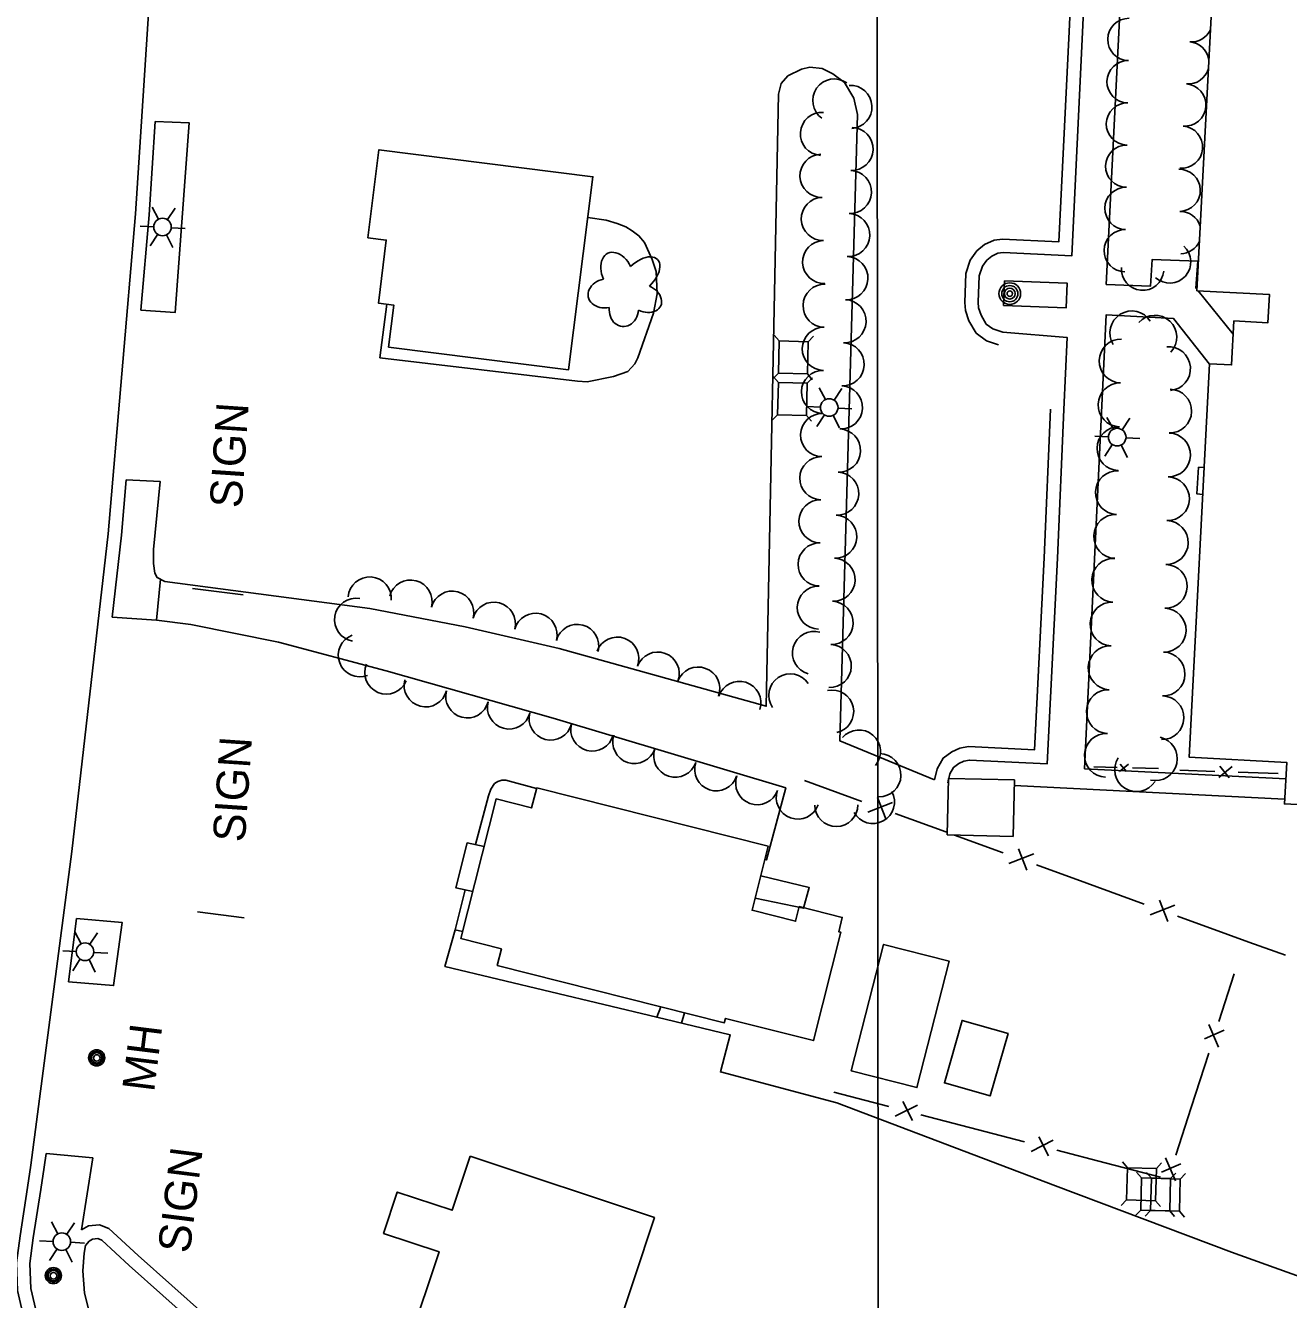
# Model space of a CAD drawing. Extents: x 189384 to 193282, y 256970 to 260388.
# Drawn here: x 190987.6 to 191223.1, y 259169.2 to 259406.6 of the extents above; entities that cross this region are included whole.
import ezdxf

# ---------------------------------------------------------------- set-up
doc = ezdxf.new("R2010")
doc.units = 0
for name, color, linetype in [('E_DRN_Grate', 7, 'Continuous'), ('E_DWY', 7, 'Continuous'), ('E_LAND_Vegetation', 7, 'Continuous'), ('E_MAP_GridLines', 7, 'Continuous'), ('E_MISCPROP', 7, 'Continuous'), ('E_MISCPROP_HvyDash', 7, 'Continuous'), ('E_MISCPROP_HvyLine', 7, 'Continuous'), ('E_MISCPROP_Railing', 7, 'Continuous'), ('E_PATH_Sidewalk', 7, 'Continuous'), ('E_RDWY', 7, 'Continuous'), ('E_UTL_AboveGroundPipe', 7, 'Continuous')]:
    doc.layers.add(name, color=color, linetype=linetype)

# ---------------------------------------------------------------- blocks, each defined once
blk = doc.blocks.new('MHO_15')
at = {"layer": 'E_DRN_Grate'}
for centre, radius in [((0.04, -0.06), 1.5), ((0.04, -0.06), 1.22), ((0.04, -0.07), 0.968), ((0.01, -0.08), 0.605)]:
    blk.add_circle(centre, radius, dxfattribs=at)
blk = doc.blocks.new('MHO_16')
at = {"layer": 'E_DRN_Grate'}
for centre, radius in [((0.04, -0.06), 1.5), ((0.04, -0.06), 1.22), ((0.04, -0.07), 0.968), ((0.01, -0.08), 0.605)]:
    blk.add_circle(centre, radius, dxfattribs=at)
blk = doc.blocks.new('MHT_14')
at = {"layer": 'E_DRN_Grate'}
blk.add_text('MH', height=6, rotation=360, dxfattribs=at).set_placement((-5.61, -3.06))
blk = doc.blocks.new('PED')
at = {"layer": 'E_UTL_AboveGroundPipe'}
for p, q in [((-2.34, 2.71), (-3.29, 3.77)), ((3.06, 2.71), (4.02, 3.77)), ((-3.29, -4.35), (-2.34, -3.29)), ((4.02, -4.35), (3.06, -3.29))]:
    blk.add_line(p, q, dxfattribs=at)
blk.add_lwpolyline([(-2.34, -3.29), (3.06, -3.29), (3.06, 2.71), (-2.34, 2.71)], close=True, dxfattribs=at)
blk = doc.blocks.new('LTP')
at = {"layer": 'E_MISCPROP'}
for p, q in [((-0.78, 1.46), (-1.98, 3.76)), ((0.86, 1.37), (2.22, 3.6)), ((-1.61, 0.09), (-4.22, 0.17)), ((1.66, 0), (4.18, -0.06)), ((-0.86, -1.4), (-2.22, -3.59)), ((0.78, -1.44), (2.02, -3.62))]:
    blk.add_line(p, q, dxfattribs=at)
blk.add_circle((0.02, 0.01), 1.64, dxfattribs=at)
blk = doc.blocks.new('POLE')
at = {"layer": 'E_MISCPROP'}
for radius in [2.02, 1.51, 1.01, 0.504]:
    blk.add_circle((0.03, -0.09), radius, dxfattribs=at)
blk = doc.blocks.new('TREE')
at = {"layer": 'E_LAND_Vegetation'}
for centre, major_axis, ratio in [((-1.07, 3.38), (0.91, -3.32), 0.782863), ((2.88, 1.66), (-3.52, -1.95), 0.691916), ((-3.74, -0.07), (3.29, -0.08), 0.832022), ((2.54, -2.64), (-3.34, 3.06), 0.560249), ((-1.48, -3.66), (1.2, 3.24), 0.716896)]:
    blk.add_ellipse(centre, major_axis=major_axis, ratio=ratio, start_param=1.570796, end_param=4.712389, dxfattribs=at)
blk = doc.blocks.new('SIGN')
at = {"layer": 'E_MISCPROP'}
blk.add_text('SIGN', height=6, rotation=0, dxfattribs=at).set_placement((0, -3))
blk = doc.blocks.new('SIGN_1')
at = {"layer": 'E_MISCPROP'}
blk.add_text('SIGN', height=6, rotation=360, dxfattribs=at).set_placement((-9.61, -3.01))

msp = doc.modelspace()

# ---------------------------------------------------------------- linework, layer by layer
at = {"layer": 'E_DWY'}
for points in [[(191169.01, 259347.09), (191166.8, 259347.84), (191164.86, 259349.29), (191163.51, 259351.61), (191162.86, 259353.49), (191162.74, 259355), (191162.95, 259360.41), (191163.78, 259362.92), (191165.02, 259364.61), (191166.44, 259365.79), (191168.22, 259366.62), (191169.77, 259366.82), (191180.31, 259366.31), (191182.18, 259405.49), (191184.13, 259447.55), (191185.9, 259490.73)], [(191169.82, 259349.45), (191167.98, 259350.08), (191166.76, 259350.99), (191165.79, 259352.65), (191165.33, 259354.01), (191165.24, 259355.05), (191165.44, 259359.96), (191166.03, 259361.76), (191166.85, 259362.88), (191167.79, 259363.66), (191168.93, 259364.19), (191169.88, 259364.31), (191182.69, 259363.69), (191184.68, 259405.37), (191186.63, 259447.44), (191188.4, 259490.63)], [(191006.37, 259321.93), (191012.7, 259321.64), (191011.49, 259308.96), (191011.47, 259306.34), (191011.72, 259304.53), (191012.18, 259303.72), (191013.58, 259303), (191051.8, 259297.98), (191069.57, 259294.53), (191087.1, 259290.48), (191125.73, 259279.75), (191128.01, 259393.82), (191128.53, 259395.79), (191129.77, 259397.26), (191132.28, 259398.5), (191133.84, 259398.85), (191136.13, 259398.59), (191138.15, 259397.63), (191140.33, 259395.99), (191142.05, 259393.07), (191142.76, 259390.06), (191139.44, 259273.33), (191157.12, 259266.03)], [(191011.76, 259388.74), (191018.1, 259388.51), (191015.49, 259353.13), (191009.1, 259353.57)], [(191054.97, 259354.7), (191053.69, 259344.69), (191090.5, 259340.33), (191092.35, 259340.22), (191097.25, 259341.2), (191099.92, 259342.17), (191101.2, 259343.55), (191101.76, 259344.69), (191104.68, 259353.02), (191105.38, 259356.62), (191105.2, 259360.8), (191104.45, 259363), (191103, 259366.16), (191101.98, 259367.43), (191100.72, 259368.33), (191099.52, 259369.1), (191097.94, 259369.71), (191095.88, 259370.32), (191092.44, 259370.86)], [(191181.22, 259335.03), (191181.83, 259348.49), (191169.82, 259349.45)], [(191157.12, 259266.03), (191157.59, 259268.09), (191158.74, 259270.09), (191160.34, 259271.22), (191161.81, 259271.94), (191163.47, 259272.22), (191175.73, 259271.62), (191177.57, 259307.44), (191178.72, 259335.14)], [(191159.75, 259266.29), (191159.94, 259267.17), (191160.63, 259268.36), (191161.62, 259269.06), (191162.58, 259269.53), (191163.62, 259269.71), (191178.1, 259269.01), (191180.06, 259307.32), (191181.22, 259335.03)], [(191003.75, 259296.38), (191012.04, 259295.81), (191018.42, 259294.98), (191034.75, 259291.71), (191054.88, 259286.33), (191086, 259277.51), (191129.37, 259264.51), (191125.77, 259251.09), (191125.47, 259251.16)], [(191159.56, 259265.48), (191159.73, 259266.22)], [(191071.52, 259253.95), (191073.96, 259263.05), (191074.37, 259264.31), (191075.03, 259265.32), (191075.7, 259265.73), (191076.42, 259265.96), (191077.16, 259265.94), (191082.89, 259264.43)], [(191067.72, 259238.05), (191069.6, 259245.5)], [(190995.6, 259228.37), (191004.01, 259227.68), (191005.61, 259239.45), (190997.14, 259240.17)], [(191105.32, 259221.78), (191119.01, 259218.52), (191117.19, 259211.6), (191138.91, 259205.83), (191179.68, 259190.35), (191212.49, 259178), (191250.88, 259164.18)], [(190998.05, 259182.13), (191000.15, 259195.57), (190991.43, 259196.39)], [(191041.42, 259147.83), (191034.49, 259154.01), (191021.16, 259166.18), (191008.62, 259177.39), (191003.17, 259182.4), (191001.43, 259183.06), (190999.35, 259182.89), (190998.05, 259182.13)], [(191039.75, 259145.97), (191032.82, 259152.15), (191019.49, 259164.33), (191006.94, 259175.54), (191001.83, 259180.24), (191001.07, 259180.52), (191000.12, 259180.44), (190999.48, 259180.07), (190998.81, 259179.24), (190998.54, 259177.81), (190998.31, 259174.49), (190998.63, 259170.35), (190999.68, 259166.21), (191001.78, 259161.45), (191004.72, 259156.99), (191007.35, 259153.66), (191010.51, 259150.69), (191013.82, 259148.31), (191019.89, 259145.1), (191026.22, 259142.62), (191030.57, 259141.21)]]:
    msp.add_lwpolyline(points, dxfattribs=at)
at = {"layer": 'E_LAND_Vegetation'}
for centre, radius, start, end in [((191193.33, 259404.03), 3.94, 89.0497, 269.0344), ((191204.99, 259407.51), 3.94, 265.5916, 334.6957), ((191204.38, 259399.66), 3.94, 9.6429, 85.5762), ((191193.2, 259396.15), 3.94, 89.0497, 269.0344), ((191204.38, 259399.66), 3.94, 265.5916, 344.4513), ((191138.42, 259392.64), 4.02, 55.0245, 235.0092), ((191141.43, 259391.45), 4.02, 273.3302, 93.3148), ((191203.78, 259391.81), 3.94, 265.5916, 85.5762), ((191193.07, 259388.28), 3.94, 89.0497, 269.0344), ((191136.11, 259386.43), 4.02, 85.9189, 265.9035), ((191141.62, 259383.62), 4.02, 267.8798, 87.8645), ((191203.17, 259383.96), 3.94, 265.5916, 85.5762), ((191136.03, 259378.61), 4.02, 91.789, 271.7737), ((191192.94, 259380.41), 3.94, 89.0497, 269.0344), ((191141.32, 259375.59), 4.02, 267.8798, 87.8645), ((191202.73, 259375.9), 3.94, 271.3648, 91.3495), ((191192.8, 259372.54), 3.94, 89.0497, 269.0344), ((191136.28, 259370.58), 4.02, 91.789, 271.7737), ((191141.01, 259367.57), 4.02, 267.5525, 87.5372), ((191202.92, 259368.03), 3.94, 18.0454, 91.3495), ((191192.67, 259364.66), 3.94, 89.0497, 269.0344), ((191136.53, 259362.54), 4.02, 91.789, 271.7737), ((191202.92, 259368.03), 3.94, 271.3648, 336.0488), ((191200.95, 259362.56), 3.94, 228.2834, 48.2681), ((191140.67, 259359.54), 4.02, 267.5525, 87.5372), ((191195.91, 259361.2), 3.94, 174.909, 354.8937), ((191136.62, 259354.4), 4.02, 88.8933, 268.878), ((191140.32, 259351.51), 4.02, 267.5525, 87.5372), ((191193.89, 259349.34), 4.08, 32.1313, 212.116), ((191198.2, 259348.53), 4.08, 317.2342, 137.2188), ((191136.47, 259346.36), 4.02, 88.8933, 268.878), ((191139.98, 259343.48), 4.02, 267.5525, 87.5372), ((191191.89, 259344.09), 4.08, 88.5722, 268.5569), ((191200.75, 259342.67), 4.08, 274.8384, 94.8231), ((191136.31, 259338.33), 4.02, 88.8933, 268.878), ((191191.69, 259335.92), 4.08, 88.5722, 268.5569), ((191139.64, 259335.44), 4.02, 267.5525, 87.5372), ((191200.96, 259334.76), 4.08, 268.574, 88.5587), ((191136.15, 259330.29), 4.02, 88.8933, 268.878), ((191139.29, 259327.41), 4.02, 267.5525, 87.5372), ((191191.48, 259327.76), 4.08, 88.5722, 268.5569), ((191200.75, 259326.59), 4.08, 268.574, 88.5587), ((191136, 259322.25), 4.02, 88.8933, 268.878), ((191138.95, 259319.38), 4.02, 267.5525, 87.5372), ((191191.21, 259319.56), 4.08, 87.6179, 267.6026), ((191200.55, 259318.42), 4.08, 268.574, 88.5587), ((191135.84, 259314.21), 4.02, 88.8933, 268.878), ((191138.6, 259311.35), 4.02, 267.5525, 87.5372), ((191190.87, 259311.4), 4.08, 87.6179, 267.6026), ((191200.34, 259310.26), 4.08, 268.574, 88.5587), ((191135.69, 259306.18), 4.02, 88.8933, 268.878), ((191138.26, 259303.32), 4.02, 267.5525, 87.5372), ((191190.53, 259303.24), 4.08, 87.6179, 267.6026), ((191200.14, 259302.09), 4.08, 268.574, 88.5587), ((191051.79, 259299.84), 4.02, 355.8605, 175.8451), ((191059.41, 259299.26), 4.02, 345.1062, 165.0909), ((191135.53, 259298.14), 4.02, 88.8933, 268.878), ((191049.23, 259295.86), 4.02, 80.2112, 260.1959), ((191067.18, 259297.19), 4.02, 345.1062, 165.0909), ((191074.95, 259295.13), 4.02, 345.1062, 165.0909), ((191082.72, 259293.06), 4.02, 345.1062, 165.0909), ((191137.91, 259295.29), 4.02, 267.5525, 87.5372), ((191190.19, 259295.07), 4.08, 87.6179, 267.6026), ((191199.93, 259293.93), 4.08, 268.574, 88.5587), ((191090.49, 259290.99), 4.02, 345.1062, 165.0909), ((191049.95, 259289.25), 4.02, 110.6208, 290.6055), ((191097.95, 259288.62), 4.02, 339.7014, 159.6861), ((191134.64, 259289.67), 4.02, 74.2741, 254.2587), ((191137.57, 259287.26), 4.02, 267.5525, 87.5372), ((191189.85, 259286.91), 4.08, 87.6179, 267.6026), ((191054.88, 259286.03), 4.02, 157.0707, 337.0554), ((191105.49, 259285.83), 4.02, 339.7014, 159.6861), ((191199.73, 259285.76), 4.08, 268.574, 88.5587), ((191113.03, 259283.04), 4.02, 339.7014, 159.6861), ((191130.22, 259281.76), 4.02, 33.9038, 213.8884), ((191062.22, 259283.65), 4.02, 165.1414, 345.126), ((191120.72, 259280.38), 4.02, 342.3555, 162.3402), ((191189.51, 259278.75), 4.08, 87.6179, 267.6026), ((191069.99, 259281.59), 4.02, 165.1414, 345.126), ((191077.76, 259279.52), 4.02, 165.1414, 345.126), ((191138.01, 259278.75), 4.02, 282.4212, 102.4059), ((191199.52, 259277.6), 4.08, 268.574, 88.5587), ((191085.53, 259277.46), 4.02, 165.1414, 345.126), ((191093.3, 259275.4), 4.02, 165.1414, 345.126), ((191101.13, 259273.08), 4.02, 161.5577, 341.5424), ((191143.02, 259271.3), 4.02, 319.8395, 139.8242), ((191189.16, 259270.59), 4.08, 87.6179, 267.6026), ((191198.29, 259269.98), 4.08, 257.4753, 77.46), ((191108.76, 259270.53), 4.02, 161.5577, 341.5424), ((191116.39, 259267.99), 4.02, 161.5577, 341.5424), ((191146.82, 259266.9), 4.02, 268.3692, 88.3539), ((191194.78, 259267.93), 4.08, 147.3836, 327.3683), ((191124.04, 259265.41), 4.02, 160.455, 340.4397), ((191131.62, 259262.72), 4.02, 160.455, 340.4397), ((191145.62, 259261.9), 4.02, 208.799, 28.7837), ((191138.79, 259261.35), 4.02, 180.2569, 0.2416)]:
    msp.add_arc(centre, radius, start, end, dxfattribs=at)
at = {"layer": 'E_MAP_GridLines'}
msp.add_line((191147.05, 258511.8), (191146.33, 259511.8), dxfattribs=at)
at = {"layer": 'E_MISCPROP'}
for p, q in [((191028.16, 259300.53), (191018.76, 259301.71)), ((191019.69, 259241.44), (191028.39, 259240.3))]:
    msp.add_line(p, q, dxfattribs=at)
at = {"layer": 'E_MISCPROP_HvyDash'}
for points in [[(191073.12, 259253.62), (191069.93, 259254.27), (191067.85, 259245.88), (191070.99, 259245.2)], [(191123.64, 259243.95), (191132.7, 259242.09), (191133.73, 259245.94), (191124.7, 259248.13)], [(191069.11, 259237.74), (191067.72, 259238.05), (191065.8, 259231.25), (191105.32, 259221.78), (191106.07, 259223.75)]]:
    msp.add_lwpolyline(points, dxfattribs=at)
at = {"layer": 'E_MISCPROP_HvyLine'}
msp.add_lwpolyline([(191249.87, 259260.11), (191222.34, 259261.53), (191222.34, 259261.53), (191222.34, 259261.53), (191222.79, 259269.29), (191222.79, 259269.29), (191204.61, 259270.23), (191204.61, 259270.23), (191208.39, 259343.59), (191208.39, 259343.59), (191208.39, 259343.59), (191212.51, 259343.38), (191212.51, 259343.38), (191212.93, 259351.57), (191219.27, 259351.24), (191219.27, 259351.24), (191219.55, 259356.51), (191219.55, 259356.51), (191219.55, 259356.51), (191206.04, 259357.2), (191209.84, 259430.83)], dxfattribs=at)
for points in [[(191093.39, 259378.45), (191093.39, 259378.45), (191053.51, 259383.48), (191053.51, 259383.48), (191051.45, 259367.07), (191054.88, 259366.64), (191054.88, 259366.64), (191054.88, 259366.64), (191053.4, 259354.9), (191056.28, 259354.53), (191056.28, 259354.53), (191056.28, 259354.53), (191055.29, 259346.69), (191088.86, 259342.46), (191088.86, 259342.46), (191093.39, 259378.45)], [(191159.49, 259255.76), (191171.75, 259255.48), (191171.99, 259266.02), (191171.99, 259266.02), (191159.73, 259266.29), (191159.73, 259266.29), (191159.73, 259266.29)], [(191082.92, 259264.57), (191126.1, 259253.66), (191126.1, 259253.66), (191126.1, 259253.66), (191123.08, 259241.72), (191131.2, 259239.67), (191131.2, 259239.67), (191131.89, 259242.42), (191139.91, 259240.39), (191139.24, 259237.73), (191139.24, 259237.73), (191139.64, 259237.63), (191139.64, 259237.63), (191134.54, 259217.42), (191118.11, 259221.57), (191118.11, 259221.57), (191118.11, 259221.57), (191117.91, 259220.76), (191117.91, 259220.76), (191075.57, 259231.45), (191076.35, 259234.54), (191076.35, 259234.54), (191068.78, 259236.45), (191068.78, 259236.45), (191068.78, 259236.45), (191075.35, 259262.46), (191081.97, 259260.79), (191081.97, 259260.79), (191081.97, 259260.79)], [(191147.6, 259235.37), (191147.6, 259235.37), (191141.59, 259211.79), (191141.59, 259211.79), (191153.83, 259208.67), (191159.83, 259232.25), (191147.6, 259235.37)], [(191162.25, 259221.18), (191162.25, 259221.18), (191158.95, 259209.54), (191158.95, 259209.54), (191167.51, 259207.11), (191170.81, 259218.75), (191170.81, 259218.75), (191162.25, 259221.18)], [(191070.49, 259195.86), (191104.88, 259184.44), (191104.88, 259184.44), (191104.88, 259184.44), (191093.43, 259149.98), (191093.43, 259149.98), (191059.17, 259161.37), (191064.72, 259178.06), (191064.72, 259178.06), (191064.72, 259178.06), (191054.38, 259181.5), (191056.93, 259189.19), (191056.93, 259189.19), (191067.14, 259185.8), (191067.14, 259185.8), (191067.14, 259185.8)]]:
    msp.add_lwpolyline(points, close=True, dxfattribs=at)
at = {"layer": 'E_MISCPROP_Railing'}
for p, q in [((191191.62, 259267.58), (191193.27, 259268.94)), ((191191.73, 259268.98), (191192.91, 259267.58)), ((191210.12, 259266.44), (191212.63, 259268.49)), ((191210.3, 259268.57), (191212.07, 259266.42)), ((191149.29, 259261.78), (191144.67, 259260)), ((191148.02, 259258.78), (191146.47, 259262.73)), ((191175.6, 259252.21), (191170.98, 259250.43)), ((191174.33, 259249.21), (191172.78, 259253.17)), ((191201.91, 259242.65), (191197.29, 259240.87)), ((191200.64, 259239.65), (191199.08, 259243.6)), ((191211.09, 259219.36), (191207.45, 259217.77)), ((191208.24, 259220.44), (191210.06, 259216.19)), ((191153.93, 259205.42), (191149.79, 259203.35)), ((191153.02, 259202.52), (191151.22, 259206.06)), ((191179.25, 259198.84), (191175.11, 259196.78)), ((191178.33, 259195.94), (191176.54, 259199.48)), ((191200.2, 259195.56), (191202.02, 259191.3)), ((191203.04, 259194.47), (191199.4, 259192.89))]:
    msp.add_line(p, q, dxfattribs=at)
for points in [[(191186.84, 259268.45), (191191.14, 259268.35)], [(191193.99, 259268.28), (191198.88, 259268.16)], [(191202.84, 259267.84), (191209.39, 259267.61)], [(191213.72, 259267.46), (191221.17, 259267.2)], [(191143.57, 259262), (191132.88, 259265.89)], [(191159.19, 259256.32), (191149.79, 259259.74)], [(191159.5, 259256.21), (191159.19, 259256.32)], [(191169.88, 259252.43), (191160.83, 259255.73)], [(191185.5, 259246.76), (191176.1, 259250.17)], [(191196.19, 259242.87), (191185.5, 259246.76)], [(191211.81, 259237.19), (191202.41, 259240.61)], [(191222.52, 259233.35), (191215.69, 259235.78), (191211.81, 259237.19)], [(191213, 259229.87), (191210.13, 259220.98)], [(191208.23, 259215.1), (191204.96, 259204.98)], [(191148.6, 259205.12), (191138.31, 259207.79)], [(191204.96, 259204.98), (191202.09, 259196.09)], [(191163.62, 259201.21), (191154.58, 259203.57)], [(191173.91, 259198.54), (191163.62, 259201.21)], [(191188.94, 259194.64), (191179.89, 259196.99)], [(191199.22, 259191.96), (191188.94, 259194.64)]]:
    msp.add_lwpolyline(points, dxfattribs=at)
at = {"layer": 'E_PATH_Sidewalk'}
for points in [[(191210.16, 259430.81), (191210.33, 259434.96), (191193.03, 259436.26), (191189.12, 259358.37), (191197.38, 259358.05), (191197.69, 259363.03), (191206.23, 259362.73), (191205.86, 259357.67), (191206.05, 259357.43)], [(191206.25, 259357.19), (191212.8, 259349.07)], [(191208.39, 259343.53), (191201.68, 259352.01), (191189.09, 259352.69), (191185.09, 259268.09), (191222.61, 259266.19)], [(191207.13, 259319.24), (191206.04, 259319.31), (191206.35, 259324.29), (191207.39, 259324.23)], [(191012.04, 259295.81), (191012.79, 259303.41)], [(191159.56, 259265.48), (191159.71, 259265.47)], [(191222.39, 259262.41), (191171.97, 259264.99)], [(191109.9, 259220.69), (191110.47, 259222.63)]]:
    msp.add_lwpolyline(points, dxfattribs=at)
msp.add_lwpolyline([(191170.16, 259359.02), (191181.85, 259358.59), (191181.68, 259354.01), (191169.99, 259354.45)], close=True, dxfattribs=at)
at = {"layer": 'E_RDWY'}
for points in [[(191048.1, 259995.99), (191043.46, 259939.63), (191039.72, 259896.92), (191035.9, 259846.97), (191033.06, 259800.26), (191028.66, 259723.54), (191025.78, 259671.21), (191024.1, 259639.83), (191022.83, 259617.71), (191020.45, 259577.04), (191019.17, 259553.9), (191017.17, 259518.52), (191013.34, 259454.66), (191012.18, 259433.77), (191008.14, 259371.5), (191003, 259311.88), (190996.25, 259252.68), (190988.62, 259194.19), (190987.97, 259190.05), (190986.58, 259181.04), (190985.91, 259175.99), (190986.1, 259170.87), (190987.75, 259163.86)], [(191011.76, 259388.74), (191010.63, 259371.32), (191009.1, 259353.57)], [(191006.37, 259321.93), (191005.49, 259311.63), (191003.75, 259296.38)], [(190997.14, 259240.17), (190995.6, 259228.37)], [(190991.43, 259196.39), (190991.09, 259193.83), (190990.44, 259189.67), (190989.05, 259180.68), (190988.41, 259175.87), (190988.59, 259171.21), (190990.15, 259164.57), (190991.53, 259160.66), (190993.85, 259156.44), (190997.01, 259152.17), (190999.96, 259148.83), (191004.67, 259144.82), (191008.44, 259142.6), (191012.62, 259140.68), (191019.96, 259138.05)]]:
    msp.add_lwpolyline(points, dxfattribs=at)

# ---------------------------------------------------------------- block references
at = {"layer": 'E_DRN_Grate'}
for name, p, xscale, yscale, rotation in [('MHT_14', (191009.23, 259213.66), 0.9999979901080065, 0.9999979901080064, 82.88508321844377), ('MHO_16', (191000.81, 259214.19), 0.9999979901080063, 0.999997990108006, 82.88508336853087)]:
    msp.add_blockref(name, p, dxfattribs=dict(at, xscale=xscale, yscale=yscale, rotation=rotation))
at = {"layer": 'E_DRN_Grate', "rotation": 80.51329697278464}
msp.add_blockref('MHO_15', (190992.73, 259173.6), dxfattribs=at)
at = {"layer": 'E_LAND_Vegetation', "rotation": 86.03297236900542}
msp.add_blockref('TREE', (191099.37, 259357.54), dxfattribs=at)
at = {"layer": 'E_MISCPROP'}
for name, p, xscale, yscale, rotation in [('LTP', (191013.17, 259369.08), 0.9999978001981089, 0.9999978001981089, 178.52107627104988), ('POLE', (191171.17, 259356.56), 0.9999978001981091, 0.9999978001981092, 178.52107345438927), ('LTP', (191137.49, 259335.44), 0.9999978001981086, 0.9999978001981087, 178.5210740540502), ('SIGN', (191024.91, 259316.77), 1.0000023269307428, 1.0000023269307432, 86.10866758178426), ('LTP', (191191.19, 259329.92), 0.9999978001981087, 0.9999978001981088, 178.52107309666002), ('SIGN', (191025.51, 259254.5), 1.0000023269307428, 1.0000023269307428, 86.10866756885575), ('LTP', (190998.72, 259234), 0.9999978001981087, 0.9999978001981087, 178.52107652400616), ('SIGN_1', (191016.42, 259187.54), 1.0000013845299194, 1.0000013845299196, 82.82594595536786), ('LTP', (190994.4, 259179.96), 0.9999978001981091, 0.9999978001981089, 178.52107659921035)]:
    msp.add_blockref(name, p, dxfattribs=dict(at, xscale=xscale, yscale=yscale, rotation=rotation))
at = {"layer": 'E_UTL_AboveGroundPipe'}
for p, xscale, yscale, rotation in [((191131.12, 259344.47), 0.9999978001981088, 0.9999978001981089, 178.5210741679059), ((191130.96, 259336.71), 0.9999978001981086, 0.9999978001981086, 178.52107417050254), ((191196.05, 259190.36), 0.9999978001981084, 0.9999978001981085, 178.52107300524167), ((191198.69, 259188.47), 0.9999978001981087, 0.9999978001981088, 178.52107295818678), ((191200.51, 259188.4), 0.9999978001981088, 0.9999978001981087, 178.52107292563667)]:
    msp.add_blockref('PED', p, dxfattribs=dict(at, xscale=xscale, yscale=yscale, rotation=rotation))

doc.saveas('drawing.dxf')
